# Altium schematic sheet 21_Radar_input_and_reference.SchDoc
size 289 x 396 mm
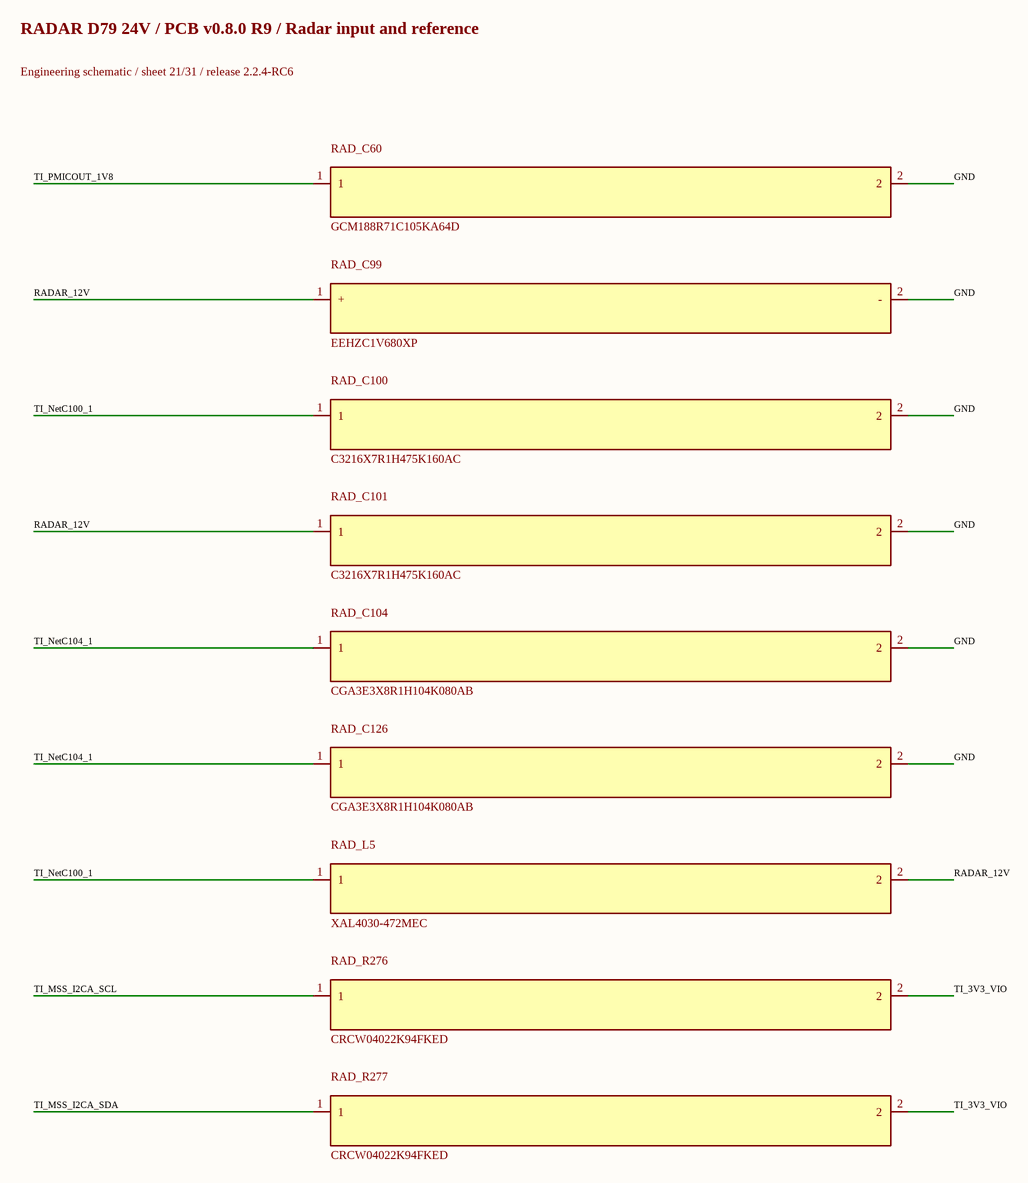
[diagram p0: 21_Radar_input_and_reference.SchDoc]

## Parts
RAD_C60  GCM188R71C105KA64D  [0603L]
RAD_C99  EEHZC1V680XP  [SM_RADIAL_6.3BMM]
RAD_C100  C3216X7R1H475K160AC  [1206_180L]
RAD_C101  C3216X7R1H475K160AC  [1206_180L]
RAD_C104  CGA3E3X8R1H104K080AB  [0603L]
RAD_C126  CGA3E3X8R1H104K080AB  [0603L]
RAD_L5  XAL4030-472MEC  [FP-XAL4030-472MEC_SMD2-MFG]
RAD_R276  CRCW04022K94FKED  [0402L]
RAD_R277  CRCW04022K94FKED  [0402L]

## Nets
GND: RAD_C60.2 RAD_C99.2(-) RAD_C100.2 RAD_C101.2 RAD_C104.2 RAD_C126.2
RADAR_12V: RAD_C99.1(+) RAD_C101.1 RAD_L5.2
TI_3V3_VIO: RAD_R276.2 RAD_R277.2
TI_MSS_I2CA_SCL: RAD_R276.1
TI_MSS_I2CA_SDA: RAD_R277.1
TI_NetC100_1: RAD_C100.1 RAD_L5.1
TI_NetC104_1: RAD_C104.1 RAD_C126.1
TI_PMICOUT_1V8: RAD_C60.1

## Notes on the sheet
- RADAR D79 24V / PCB v0.8.0 R9 / Radar input and reference
- Engineering schematic / sheet 21/31 / release 2.2.4-RC6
